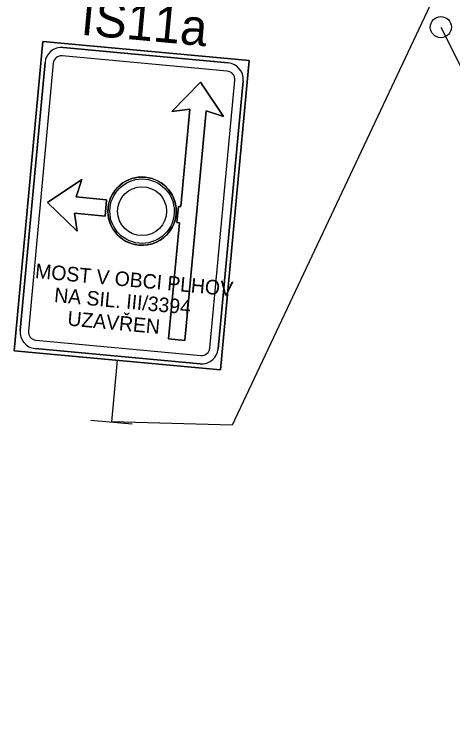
# Model space of a CAD drawing. Extents: x -688893 to -679983, y -1088371 to -1075771.
# Drawn here: x -685055 to -684417, y -1082638 to -1081610 of the extents above; entities that cross this region are included whole.
import ezdxf

# ---------------------------------------------------------------- set-up
doc = ezdxf.new("R2010")
doc.units = 0
for name, color, linetype in [('SDZ', 7, 'Continuous'), ('SDZ ozn', 7, 'Continuous'), ('SDZ plochy', 7, 'Continuous'), ('SDZ symbol', 7, 'Continuous')]:
    doc.layers.add(name, color=color, linetype=linetype)

msp = doc.modelspace()

# ---------------------------------------------------------------- linework, layer by layer
at = {"layer": 'SDZ'}
for p, q in [((-685013, -1081649.7), (-685054.6, -1082099.1)), ((-684713.4, -1081677.4), (-685013, -1081649.7)), ((-684743.9, -1081680.6), (-684983.6, -1081658.4)), ((-684745, -1081692.6), (-684984.7, -1081670.4)), ((-685009.8, -1081680.2), (-685045.8, -1082069.7)), ((-684997.8, -1081681.3), (-685033.9, -1082070.8)), ((-684755, -1082126.8), (-684713.4, -1081677.4)), ((-684770.2, -1082095.2), (-684734.1, -1081705.7)), ((-684758.2, -1082096.3), (-684722.1, -1081706.8)), ((-685023, -1082083.9), (-684783.3, -1082106.1)), ((-685024.1, -1082095.9), (-684784.4, -1082118.1)), ((-685054.6, -1082099.1), (-684755, -1082126.8)), ((-684904.8, -1082113), (-684913.1, -1082202.6)), ((-684943, -1082199.8), (-684883.2, -1082205.3))]:
    msp.add_line(p, q, dxfattribs=at)
for points in [[(-684434.7, -1081563.5), (-684738.1, -1082207.5), (-684913.1, -1082202.6)], [(-684434.8, -1081628.8), (-683939.8, -1082615.4), (-683772.5, -1082638.4)]]:
    msp.add_lwpolyline(points, dxfattribs=at)
for centre, radius in [((-684434.8, -1081628.8), 15.4), ((-684868.8, -1081896.3), 49.6), ((-684868.8, -1081896.3), 46.8), ((-684868.8, -1081896.3), 35.5)]:
    msp.add_circle(centre, radius, dxfattribs=at)
for centre, radius, start, end in [((-684985.8, -1081682.4), 24.1, 84.707, 174.707), ((-684985.8, -1081682.4), 12, 84.707, 174.707), ((-684746.1, -1081704.6), 24.1, 354.707, 84.707), ((-684746.1, -1081704.6), 12, 354.707, 84.707), ((-685021.9, -1082071.9), 24.1, 174.707, 264.707), ((-685021.9, -1082071.9), 12, 174.707, 264.707), ((-684782.2, -1082094.1), 24.1, 264.707, 354.707), ((-684782.2, -1082094.1), 12, 264.707, 354.707)]:
    msp.add_arc(centre, radius, start, end, dxfattribs=at)
at = {"layer": 'SDZ plochy'}
for p, q in [((-685054.6, -1082099.1), (-685013, -1081649.7)), ((-685013, -1081649.7), (-685054.6, -1082099.1)), ((-685013, -1081649.7), (-684713.4, -1081677.4)), ((-684713.4, -1081677.4), (-685013, -1081649.7)), ((-684983.6, -1081658.4), (-684743.9, -1081680.6)), ((-684743.9, -1081680.6), (-684983.6, -1081658.4)), ((-684983.6, -1081658.4), (-684743.9, -1081680.6)), ((-684745, -1081692.6), (-684984.7, -1081670.4)), ((-684745, -1081692.6), (-684984.7, -1081670.4)), ((-685045.8, -1082069.7), (-685009.8, -1081680.2)), ((-685009.8, -1081680.2), (-685045.8, -1082069.7)), ((-685045.8, -1082069.7), (-685009.8, -1081680.2)), ((-684997.8, -1081681.3), (-685033.9, -1082070.8)), ((-684997.8, -1081681.3), (-685033.9, -1082070.8)), ((-684713.4, -1081677.4), (-684755, -1082126.8)), ((-684755, -1082126.8), (-684713.4, -1081677.4)), ((-684770.2, -1082095.2), (-684734.1, -1081705.7)), ((-684770.2, -1082095.2), (-684734.1, -1081705.7)), ((-684722.1, -1081706.8), (-684758.2, -1082096.3)), ((-684758.2, -1082096.3), (-684722.1, -1081706.8)), ((-684722.1, -1081706.8), (-684758.2, -1082096.3)), ((-684783.9, -1081708.7), (-684825.6, -1081751.6)), ((-684825.6, -1081751.6), (-684783.9, -1081708.7)), ((-684750.4, -1081758.6), (-684783.9, -1081708.7)), ((-684783.9, -1081708.7), (-684750.4, -1081758.6)), ((-684825.6, -1081751.6), (-684799.3, -1081748)), ((-684799.3, -1081748), (-684825.6, -1081751.6)), ((-684799.3, -1081748), (-684812.4, -1081889.6)), ((-684812.4, -1081889.6), (-684799.3, -1081748)), ((-684806.5, -1082084), (-684775.6, -1081750.2)), ((-684775.6, -1081750.2), (-684806.5, -1082084)), ((-684775.6, -1081750.2), (-684750.4, -1081758.6)), ((-684750.4, -1081758.6), (-684775.6, -1081750.2)), ((-684956.3, -1081850.3), (-685006.2, -1081883.7)), ((-685006.2, -1081883.7), (-684956.3, -1081850.3)), ((-684964.6, -1081875.5), (-684956.3, -1081850.3)), ((-684956.3, -1081850.3), (-684964.6, -1081875.5)), ((-684920.4, -1081879.6), (-684964.6, -1081875.5)), ((-684964.6, -1081875.5), (-684920.4, -1081879.6)), ((-684922.6, -1081903.3), (-684920.4, -1081879.6)), ((-684920.4, -1081879.6), (-684922.6, -1081903.3)), ((-685006.2, -1081883.7), (-684963.2, -1081925.5)), ((-684963.2, -1081925.5), (-685006.2, -1081883.7)), ((-684816, -1081889.3), (-684818.2, -1081912.9)), ((-684818.2, -1081912.9), (-684816, -1081889.3)), ((-684812.4, -1081889.6), (-684816, -1081889.3)), ((-684816, -1081889.3), (-684812.4, -1081889.6)), ((-684963.2, -1081925.5), (-684966.8, -1081899.2)), ((-684966.8, -1081899.2), (-684922.6, -1081903.3)), ((-684966.8, -1081899.2), (-684963.2, -1081925.5)), ((-684922.6, -1081903.3), (-684966.8, -1081899.2)), ((-684814.6, -1081913.3), (-684830.2, -1082081.8)), ((-684830.2, -1082081.8), (-684814.6, -1081913.3)), ((-684818.2, -1081912.9), (-684814.6, -1081913.3)), ((-684814.6, -1081913.3), (-684818.2, -1081912.9)), ((-685023, -1082083.9), (-684783.3, -1082106.1)), ((-685023, -1082083.9), (-684783.3, -1082106.1)), ((-684830.2, -1082081.8), (-684806.5, -1082084)), ((-684806.5, -1082084), (-684830.2, -1082081.8)), ((-684784.4, -1082118.1), (-685024.1, -1082095.9)), ((-685024.1, -1082095.9), (-684784.4, -1082118.1)), ((-684784.4, -1082118.1), (-685024.1, -1082095.9)), ((-684755, -1082126.8), (-685054.6, -1082099.1)), ((-685054.6, -1082099.1), (-684755, -1082126.8))]:
    msp.add_line(p, q, dxfattribs=at)
for radius in [46.8, 46.8, 35.5, 35.5]:
    msp.add_circle((-684868.8, -1081896.3), radius, dxfattribs=at)
for centre, radius, start, end in [((-684985.8, -1081682.4), 24.1, 84.707, 174.707), ((-684985.8, -1081682.4), 24.1, 84.707, 174.707), ((-684985.8, -1081682.4), 24.1, 84.707, 174.707), ((-684985.8, -1081682.4), 12, 84.707, 174.707), ((-684985.8, -1081682.4), 12, 84.707, 174.707), ((-684746.1, -1081704.6), 24.1, 354.707, 84.707), ((-684746.1, -1081704.6), 24.1, 354.707, 84.707), ((-684746.1, -1081704.6), 24.1, 354.707, 84.707), ((-684746.1, -1081704.6), 12, 354.707, 84.707), ((-684746.1, -1081704.6), 12, 354.707, 84.707), ((-684868.8, -1081896.3), 49.6, 354.707, 174.707), ((-684868.8, -1081896.3), 49.6, 354.707, 174.707), ((-684868.8, -1081896.3), 49.6, 174.707, 354.707), ((-684868.8, -1081896.3), 49.6, 174.707, 354.707), ((-685021.9, -1082071.9), 24.1, 174.707, 264.707), ((-685021.9, -1082071.9), 24.1, 174.707, 264.707), ((-685021.9, -1082071.9), 24.1, 174.707, 264.707), ((-685021.9, -1082071.9), 12, 174.707, 264.707), ((-685021.9, -1082071.9), 12, 174.707, 264.707), ((-684782.2, -1082094.1), 24.1, 264.707, 354.707), ((-684782.2, -1082094.1), 24.1, 264.707, 354.707), ((-684782.2, -1082094.1), 24.1, 264.707, 354.707), ((-684782.2, -1082094.1), 12, 264.707, 354.707), ((-684782.2, -1082094.1), 12, 264.707, 354.707)]:
    msp.add_arc(centre, radius, start, end, dxfattribs=at)
at = {"layer": 'SDZ symbol'}
for p, q in [((-684783.9, -1081708.7), (-684825.6, -1081751.6)), ((-684750.4, -1081758.6), (-684783.9, -1081708.7)), ((-684825.6, -1081751.6), (-684799.3, -1081748)), ((-684799.3, -1081748), (-684812.4, -1081889.6)), ((-684806.5, -1082084), (-684775.6, -1081750.2)), ((-684775.6, -1081750.2), (-684750.4, -1081758.6)), ((-684956.3, -1081850.3), (-685006.2, -1081883.7)), ((-684964.6, -1081875.5), (-684956.3, -1081850.3)), ((-684920.4, -1081879.6), (-684964.6, -1081875.5)), ((-684922.6, -1081903.3), (-684920.4, -1081879.6)), ((-685006.2, -1081883.7), (-684963.2, -1081925.5)), ((-684816, -1081889.3), (-684818.2, -1081912.9)), ((-684812.4, -1081889.6), (-684816, -1081889.3)), ((-684963.2, -1081925.5), (-684966.8, -1081899.2)), ((-684922.6, -1081903.3), (-684966.8, -1081899.2)), ((-684814.6, -1081913.3), (-684830.2, -1082081.8)), ((-684814.6, -1081913.3), (-684818.2, -1081912.9)), ((-684830.2, -1082081.8), (-684806.5, -1082084))]:
    msp.add_line(p, q, dxfattribs=at)
msp.add_circle((-684868.8, -1081896.3), 49.6, dxfattribs=at)

# ---------------------------------------------------------------- texts
at = {"layer": 'SDZ ozn'}
msp.add_text('IS11a', height=52.5, rotation=354.707, dxfattribs=at).set_placement((-684959, -1081639.7))
at = {"layer": 'SDZ symbol'}
for s, height, p in [('MOST V OBCI PLHOV', 21.084, (-685024.8, -1081993.3)), ('NA SIL. III/3394', 21.084, (-684997.1, -1082028.2)), ('UZAVŘEN', 21.08, (-684977.9, -1082062.3))]:
    msp.add_text(s, height=height, rotation=354.707, dxfattribs=at).set_placement(p)

doc.saveas('drawing.dxf')
